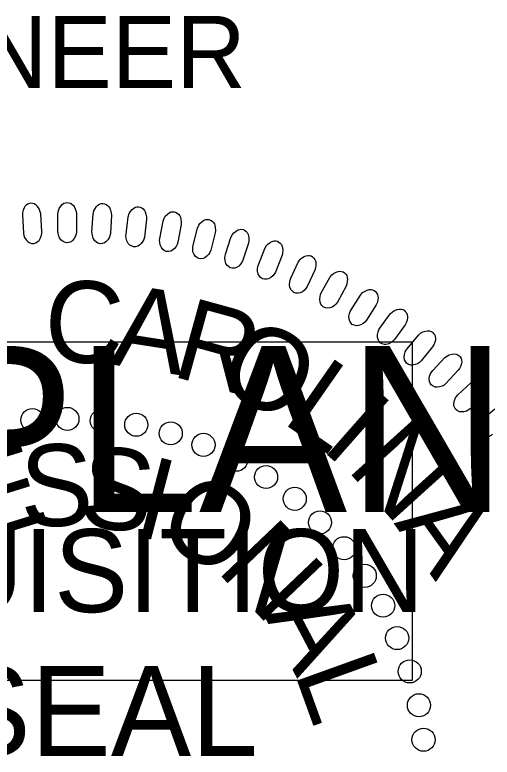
# Model space of a CAD drawing. Extents: x 505602 to 507286, y 483109 to 484209.
# Drawn here: x 507215 to 507248.1, y 484097.2 to 484148.7 of the extents above; entities that cross this region are included whole.
import ezdxf

# ---------------------------------------------------------------- set-up
doc = ezdxf.new("R2010")
doc.units = 0
for name, color, linetype in [('Sheet PE Seal Cell', 7, 'Continuous'), ('Sheet Profile CELL', 7, 'Continuous'), ('Sheet Sticker Incomplete CELL', 7, 'Continuous')]:
    doc.layers.add(name, color=color, linetype=linetype)

msp = doc.modelspace()

# ---------------------------------------------------------------- linework, layer by layer
at = {"layer": 'Sheet PE Seal Cell'}
for points in [[(507216.92, 484133.668), (507216.843, 484134.892), (507216.792, 484135.109), (507216.731, 484135.245), (507216.609, 484135.407), (507216.505, 484135.511), (507216.388, 484135.583), (507216.281, 484135.617), (507216.168, 484135.629), (507216.057, 484135.602), (507215.94, 484135.565), (507215.839, 484135.499), (507215.741, 484135.393), (507215.687, 484135.309), (507215.628, 484135.156), (507215.58, 484134.973), (507215.568, 484134.813), (507215.639, 484133.558), (507215.671, 484133.39), (507215.725, 484133.254), (507215.824, 484133.1), (507215.945, 484132.968), (507216.047, 484132.894), (507216.208, 484132.844), (507216.358, 484132.833), (507216.505, 484132.883), (507216.606, 484132.939), (507216.727, 484133.047), (507216.835, 484133.223), (507216.891, 484133.407), (507216.913, 484133.538)], [(507218.035, 484133.677), (507218.035, 484134.903), (507218.073, 484135.123), (507218.126, 484135.263), (507218.238, 484135.432), (507218.335, 484135.542), (507218.447, 484135.622), (507218.551, 484135.661), (507218.664, 484135.681), (507218.776, 484135.661), (507218.896, 484135.632), (507219, 484135.572), (507219.105, 484135.472), (507219.165, 484135.392), (507219.232, 484135.242), (507219.292, 484135.063), (507219.314, 484134.903), (507219.321, 484133.647), (507219.299, 484133.477), (507219.253, 484133.338), (507219.164, 484133.178), (507219.052, 484133.038), (507218.954, 484132.959), (507218.797, 484132.899), (507218.648, 484132.879), (507218.499, 484132.919), (507218.394, 484132.969), (507218.266, 484133.068), (507218.147, 484133.238), (507218.08, 484133.418), (507218.05, 484133.548)], [(507220.394, 484133.65), (507220.472, 484134.875), (507220.522, 484135.092), (507220.584, 484135.227), (507220.707, 484135.39), (507220.81, 484135.493), (507220.927, 484135.566), (507221.034, 484135.598), (507221.148, 484135.611), (507221.258, 484135.584), (507221.376, 484135.547), (507221.476, 484135.481), (507221.575, 484135.375), (507221.629, 484135.291), (507221.687, 484135.138), (507221.735, 484134.955), (507221.748, 484134.794), (507221.675, 484133.539), (507221.643, 484133.372), (507221.589, 484133.235), (507221.489, 484133.082), (507221.369, 484132.95), (507221.267, 484132.876), (507221.106, 484132.826), (507220.955, 484132.815), (507220.809, 484132.865), (507220.708, 484132.922), (507220.587, 484133.029), (507220.479, 484133.205), (507220.423, 484133.389), (507220.401, 484133.521)], [(507222.757, 484133.475), (507222.911, 484134.692), (507222.975, 484134.906), (507223.045, 484135.037), (507223.177, 484135.191), (507223.288, 484135.288), (507223.409, 484135.353), (507223.518, 484135.38), (507223.631, 484135.385), (507223.74, 484135.351), (507223.855, 484135.307), (507223.951, 484135.234), (507224.043, 484135.122), (507224.092, 484135.035), (507224.141, 484134.878), (507224.176, 484134.693), (507224.179, 484134.532), (507224.028, 484133.284), (507223.985, 484133.119), (507223.923, 484132.986), (507223.814, 484132.839), (507223.685, 484132.715), (507223.579, 484132.648), (507223.415, 484132.608), (507223.265, 484132.607), (507223.121, 484132.665), (507223.024, 484132.727), (507222.91, 484132.843), (507222.812, 484133.026), (507222.769, 484133.213), (507222.755, 484133.345)], [(507225.096, 484133.189), (507225.326, 484134.394), (507225.404, 484134.602), (507225.482, 484134.729), (507225.624, 484134.875), (507225.74, 484134.964), (507225.865, 484135.022), (507225.975, 484135.041), (507226.089, 484135.04), (507226.195, 484134.999), (507226.307, 484134.947), (507226.399, 484134.869), (507226.483, 484134.751), (507226.527, 484134.662), (507226.565, 484134.502), (507226.59, 484134.315), (507226.582, 484134.153), (507226.354, 484132.918), (507226.299, 484132.756), (507226.229, 484132.627), (507226.111, 484132.487), (507225.975, 484132.371), (507225.864, 484132.311), (507225.699, 484132.282), (507225.548, 484132.29), (507225.409, 484132.357), (507225.316, 484132.426), (507225.21, 484132.548), (507225.124, 484132.737), (507225.091, 484132.925), (507225.087, 484133.059)], [(507227.402, 484132.715), (507227.707, 484133.903), (507227.797, 484134.106), (507227.883, 484134.229), (507228.034, 484134.365), (507228.155, 484134.447), (507228.284, 484134.496), (507228.395, 484134.509), (507228.509, 484134.501), (507228.612, 484134.453), (507228.721, 484134.394), (507228.807, 484134.31), (507228.883, 484134.188), (507228.922, 484134.096), (507228.949, 484133.934), (507228.963, 484133.745), (507228.945, 484133.585), (507228.639, 484132.366), (507228.575, 484132.208), (507228.496, 484132.084), (507228.37, 484131.951), (507228.227, 484131.844), (507228.113, 484131.791), (507227.946, 484131.772), (507227.796, 484131.79), (507227.662, 484131.866), (507227.573, 484131.94), (507227.474, 484132.068), (507227.4, 484132.262), (507227.38, 484132.453), (507227.383, 484132.586)], [(507229.651, 484132.093), (507230.031, 484133.26), (507230.134, 484133.457), (507230.227, 484133.573), (507230.386, 484133.7), (507230.513, 484133.774), (507230.644, 484133.816), (507230.756, 484133.821), (507230.869, 484133.805), (507230.969, 484133.751), (507231.073, 484133.686), (507231.155, 484133.597), (507231.223, 484133.47), (507231.255, 484133.375), (507231.273, 484133.212), (507231.274, 484133.023), (507231.247, 484132.864), (507230.865, 484131.667), (507230.791, 484131.512), (507230.705, 484131.394), (507230.571, 484131.269), (507230.42, 484131.172), (507230.304, 484131.126), (507230.136, 484131.117), (507229.987, 484131.145), (507229.858, 484131.229), (507229.774, 484131.309), (507229.684, 484131.443), (507229.622, 484131.641), (507229.614, 484131.833), (507229.626, 484131.965)], [(507231.935, 484131.358), (507232.387, 484132.498), (507232.502, 484132.689), (507232.602, 484132.799), (507232.769, 484132.916), (507232.9, 484132.982), (507233.034, 484133.015), (507233.145, 484133.013), (507233.257, 484132.991), (507233.353, 484132.931), (507233.454, 484132.859), (507233.529, 484132.764), (507233.59, 484132.633), (507233.616, 484132.537), (507233.624, 484132.373), (507233.613, 484132.184), (507233.575, 484132.028), (507233.119, 484130.856), (507233.035, 484130.707), (507232.942, 484130.594), (507232.8, 484130.479), (507232.645, 484130.39), (507232.525, 484130.352), (507232.357, 484130.354), (507232.211, 484130.391), (507232.086, 484130.483), (507232.007, 484130.568), (507231.926, 484130.707), (507231.878, 484130.909), (507231.881, 484131.101), (507231.901, 484131.232)], [(507234.176, 484130.424), (507234.699, 484131.534), (507234.826, 484131.716), (507234.933, 484131.82), (507235.107, 484131.926), (507235.241, 484131.984), (507235.376, 484132.008), (507235.488, 484132), (507235.598, 484131.97), (507235.691, 484131.904), (507235.787, 484131.826), (507235.856, 484131.728), (507235.908, 484131.592), (507235.928, 484131.495), (507235.925, 484131.331), (507235.903, 484131.143), (507235.855, 484130.989), (507235.326, 484129.849), (507235.234, 484129.705), (507235.134, 484129.598), (507234.984, 484129.492), (507234.824, 484129.413), (507234.701, 484129.382), (507234.534, 484129.395), (507234.39, 484129.441), (507234.273, 484129.541), (507234.199, 484129.63), (507234.126, 484129.775), (507234.091, 484129.979), (507234.106, 484130.17), (507234.134, 484130.3)], [(507236.3, 484129.409), (507236.891, 484130.484), (507237.03, 484130.657), (507237.143, 484130.755), (507237.323, 484130.849), (507237.461, 484130.899), (507237.598, 484130.914), (507237.709, 484130.899), (507237.816, 484130.862), (507237.905, 484130.791), (507237.995, 484130.707), (507238.058, 484130.604), (507238.102, 484130.466), (507238.116, 484130.368), (507238.103, 484130.204), (507238.068, 484130.018), (507238.012, 484129.867), (507237.412, 484128.763), (507237.311, 484128.625), (507237.204, 484128.524), (507237.049, 484128.428), (507236.883, 484128.359), (507236.759, 484128.336), (507236.593, 484128.36), (507236.452, 484128.414), (507236.34, 484128.521), (507236.273, 484128.616), (507236.21, 484128.764), (507236.187, 484128.97), (507236.214, 484129.16), (507236.25, 484129.288)], [(507238.358, 484128.224), (507239.016, 484129.259), (507239.165, 484129.425), (507239.284, 484129.514), (507239.469, 484129.598), (507239.61, 484129.638), (507239.748, 484129.645), (507239.857, 484129.623), (507239.963, 484129.579), (507240.047, 484129.503), (507240.131, 484129.413), (507240.188, 484129.307), (507240.223, 484129.166), (507240.23, 484129.067), (507240.207, 484128.904), (507240.161, 484128.721), (507240.095, 484128.574), (507239.427, 484127.509), (507239.317, 484127.378), (507239.205, 484127.285), (507239.044, 484127.198), (507238.874, 484127.14), (507238.749, 484127.124), (507238.584, 484127.158), (507238.448, 484127.222), (507238.343, 484127.335), (507238.281, 484127.434), (507238.227, 484127.586), (507238.218, 484127.793), (507238.257, 484127.981), (507238.301, 484128.106)], [(507240.358, 484126.951), (507241.079, 484127.943), (507241.238, 484128.099), (507241.363, 484128.181), (507241.553, 484128.252), (507241.696, 484128.283), (507241.834, 484128.282), (507241.942, 484128.253), (507242.045, 484128.203), (507242.124, 484128.121), (507242.202, 484128.027), (507242.252, 484127.917), (507242.278, 484127.774), (507242.28, 484127.674), (507242.246, 484127.514), (507242.189, 484127.334), (507242.113, 484127.191), (507241.38, 484126.171), (507241.262, 484126.047), (507241.144, 484125.96), (507240.978, 484125.884), (507240.805, 484125.836), (507240.679, 484125.829), (507240.517, 484125.873), (507240.385, 484125.945), (507240.287, 484126.065), (507240.232, 484126.167), (507240.187, 484126.322), (507240.191, 484126.53), (507240.242, 484126.715), (507240.294, 484126.837)], [(507242.252, 484125.534), (507243.035, 484126.479), (507243.203, 484126.625), (507243.332, 484126.699), (507243.527, 484126.758), (507243.672, 484126.781), (507243.809, 484126.77), (507243.915, 484126.735), (507244.014, 484126.678), (507244.088, 484126.592), (507244.161, 484126.492), (507244.203, 484126.379), (507244.22, 484126.236), (507244.216, 484126.136), (507244.172, 484125.978), (507244.104, 484125.802), (507244.02, 484125.664), (507243.224, 484124.692), (507243.098, 484124.575), (507242.974, 484124.496), (507242.804, 484124.431), (507242.628, 484124.394), (507242.502, 484124.395), (507242.343, 484124.449), (507242.216, 484124.529), (507242.126, 484124.655), (507242.077, 484124.76), (507242.043, 484124.918), (507242.059, 484125.124), (507242.122, 484125.306), (507242.182, 484125.425)], [(507244.024, 484124.02), (507244.864, 484124.914), (507245.041, 484125.049), (507245.175, 484125.115), (507245.373, 484125.162), (507245.519, 484125.175), (507245.655, 484125.156), (507245.759, 484125.114), (507245.855, 484125.051), (507245.922, 484124.96), (507245.989, 484124.856), (507246.025, 484124.741), (507246.032, 484124.597), (507246.022, 484124.497), (507245.968, 484124.342), (507245.889, 484124.171), (507245.796, 484124.039), (507244.94, 484123.118), (507244.808, 484123.01), (507244.68, 484122.939), (507244.505, 484122.885), (507244.328, 484122.859), (507244.202, 484122.868), (507244.047, 484122.932), (507243.924, 484123.019), (507243.843, 484123.151), (507243.801, 484123.259), (507243.776, 484123.418), (507243.805, 484123.624), (507243.879, 484123.801), (507243.946, 484123.916)], [(507245.768, 484122.327), (507246.663, 484123.166), (507246.848, 484123.289), (507246.986, 484123.347), (507247.186, 484123.381), (507247.333, 484123.385), (507247.467, 484123.358), (507247.569, 484123.309), (507247.66, 484123.241), (507247.722, 484123.145), (507247.782, 484123.038), (507247.81, 484122.921), (507247.809, 484122.776), (507247.791, 484122.678), (507247.728, 484122.526), (507247.639, 484122.36), (507247.538, 484122.234), (507246.626, 484121.369), (507246.487, 484121.269), (507246.355, 484121.206), (507246.178, 484121.163), (507245.999, 484121.149), (507245.874, 484121.165), (507245.723, 484121.239), (507245.606, 484121.334), (507245.533, 484121.47), (507245.498, 484121.581), (507245.483, 484121.742), (507245.525, 484121.945), (507245.61, 484122.117), (507245.684, 484122.227)]]:
    msp.add_lwpolyline(points, close=True, dxfattribs=at)
msp.add_lwpolyline([(507248.177, 484119.571), (507248.032, 484119.48), (507247.895, 484119.426), (507247.715, 484119.393), (507247.536, 484119.39), (507247.413, 484119.414), (507247.266, 484119.497), (507247.156, 484119.6), (507247.092, 484119.74), (507247.063, 484119.853), (507247.059, 484120.014), (507247.114, 484120.214), (507247.209, 484120.381), (507247.29, 484120.487), (507247.38, 484120.581), (507248.326, 484121.362)], dxfattribs=at)
for centre in [(507216.263, 484120.581), (507218.692, 484120.66), (507221.081, 484120.54), (507223.47, 484120.26), (507225.858, 484119.662), (507228.127, 484118.864), (507230.396, 484117.828), (507232.466, 484116.632), (507234.456, 484115.118), (507236.208, 484113.484), (507237.879, 484111.691), (507239.312, 484109.778), (507240.585, 484107.706), (507241.557, 484105.457), (507242.432, 484103.146), (507243.069, 484100.795), (507243.386, 484098.405)]:
    msp.add_circle(centre, 0.801, dxfattribs=at)
at = {"layer": 'Sheet Sticker Incomplete CELL'}
msp.add_lwpolyline([(507095.597, 484102.505), (507095.597, 484126.005), (507242.597, 484126.005), (507242.597, 484102.505)], close=True, dxfattribs=at)

# ---------------------------------------------------------------- texts
at = {"layer": 'Sheet PE Seal Cell'}
for s, height, rotation, p in [('C', 5.669, 357.5877, (507217.01, 484124.672)), ('A', 5.669, 351.0983, (507221.585, 484124.463)), ('R', 5.669, 344.609, (507225.792, 484123.669)), ('O', 5.669, 331.6302, (507228.747, 484123.015)), ('L', 5.669, 325.1409, (507233.48, 484120.484)), ('I', 5.669, 318.6515, (507236.173, 484118.631)), ('N', 5.669, 312.1622, (507237.978, 484117.211)), ('E', 5.669, 17.1686, (507212.701, 484112.219)), ('S', 5.669, 1.289, (507215.468, 484113.179)), ('S', 5.669, 353.3492, (507219.329, 484113.28)), ('I', 5.669, 345.4094, (507223.13, 484112.648)), ('O', 5.669, 329.5298, (507224.633, 484112.476)), ('A', 5.669, 305.6728, (507241.298, 484113.43)), ('N', 5.669, 313.6502, (507228.945, 484110.172)), ('A', 5.669, 297.7707, (507232.282, 484107.091)), ('L', 5.669, 289.8309, (507234.406, 484103.097)), ('SEAL', 6.2363, 359.9814, (507210.585, 484097.285))]:
    msp.add_text(s, height=height, rotation=rotation, dxfattribs=at).set_placement(p)
at = {"layer": 'Sheet Profile CELL'}
msp.add_text('ENGINEER', height=5.0001, dxfattribs=at).set_placement((507196.142, 484143.624))
at = {"layer": 'Sheet Sticker Incomplete CELL'}
for s, height, p in [('INCOMPLETE PLANS', 11.52, (507104.547, 484114.205)), ('DO NOT USE FOR R/W ACQUISITION', 5.76, (507107.797, 484107.255))]:
    msp.add_text(s, height=height, dxfattribs=at).set_placement(p)

doc.saveas('drawing.dxf')
